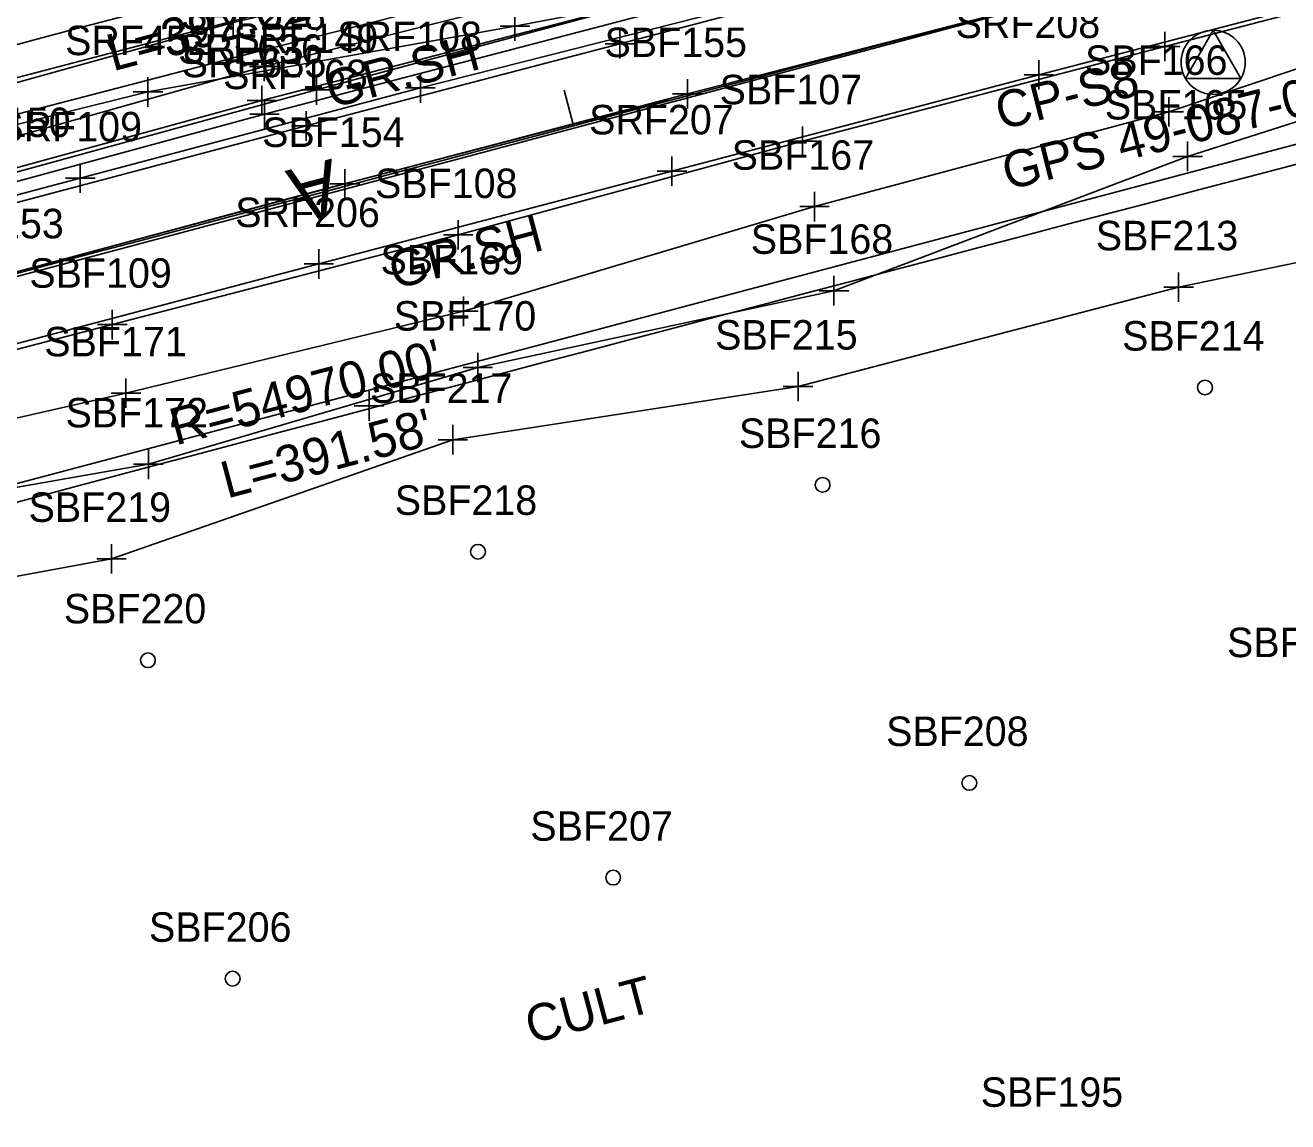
# Model space of a CAD drawing. Extents: x 818717 to 846077, y 440014 to 541392.
# Drawn here: x 831949.3 to 832120.6, y 493055.7 to 493204.5 of the extents above; entities that cross this region are included whole.
import ezdxf

# ---------------------------------------------------------------- set-up
doc = ezdxf.new("R2010")
doc.units = 0
for name, color, linetype in [('SURVEY - CENTERLINE - Preliminary', 7, 'Continuous'), ('SURVEY - CENTERLINE - Preliminary Text', 7, 'Continuous'), ('SURVEY - CONTROL with Text', 7, 'Continuous'), ('SURVEY - DRAINAGE - Area Shapes', 7, 'Continuous'), ('SURVEY - DTM - Breaklines', 7, 'Continuous'), ('SURVEY - DTM - Breaklines - Points - Locators', 7, 'Continuous'), ('SURVEY - DTM - Breaklines - Points - Numbers', 7, 'Continuous'), ('SURVEY - DTM - Spot Points - Locators', 7, 'Continuous'), ('SURVEY - DTM - Spot Points - Point Numbers', 7, 'Continuous'), ('SURVEY - PROPERTY - ROW Lines', 7, 'Continuous'), ('SURVEY - PROPERTY - ROW Lines - Points - Locators', 7, 'Continuous'), ('SURVEY - PROPERTY - ROW Lines Text', 7, 'Continuous'), ('SURVEY - TRAFFIC CONTROL - Pavement Marking - Points - Locators', 7, 'Continuous'), ('SURVEY - TRAFFIC CONTROL - Pavement Marking - Points - Numbers', 7, 'Continuous'), ('SURVEY - TRAFFIC CONTROL - Pavement Marking with Text', 7, 'Continuous'), ('SURVEY - TRANSPORTATION - Features Text', 7, 'Continuous'), ('SURVEY - TRANSPORTATION - Roads', 7, 'Continuous'), ('SURVEY - TRANSPORTATION - Roads - Points - Locators', 7, 'Continuous'), ('SURVEY - TRANSPORTATION - Roads - Points - Numbers', 7, 'Continuous'), ('SURVEY - UTILITIES - Electric (Overhead) with Text', 7, 'Continuous'), ('SURVEY - UTILITIES - Telephone (Underground) - Points - Locators', 7, 'Continuous'), ('SURVEY - UTILITIES - Telephone (Underground) - Points - Numbers', 7, 'Continuous'), ('SURVEY - UTILITIES - Telephone (Underground) with Text', 7, 'Continuous'), ('SURVEY - UTILITIES - Water with Text', 7, 'Continuous'), ('SURVEY - VEGETATION - Features - Points - Locators', 7, 'Continuous'), ('SURVEY - VEGETATION - Features - Points - Numbers', 7, 'Continuous'), ('SURVEY - VEGETATION - Features with Text', 7, 'Continuous')]:
    doc.layers.add(name, color=color, linetype=linetype)

msp = doc.modelspace()

# ---------------------------------------------------------------- linework, layer by layer
at = {"layer": 'SURVEY - CENTERLINE - Preliminary'}
msp.add_arc((846074.62, 440015.93), 55000, 104.635499, 105.043654, dxfattribs=at)
msp.add_arc((846074.62, 440015.93), 55000, 104.635499, 105.043654, dxfattribs=at)
msp.add_arc((846074.62, 440015.93), 55000, 104.635499, 105.043654, dxfattribs=at)
at = {"layer": 'SURVEY - CENTERLINE - Preliminary Text'}
for p, q in [((832023.71, 493190.85), (832022.44, 493195.69)), ((831988.29, 493181.84), (832036.66, 493194.47)), ((831940, 493168.86), (831988.29, 493181.84))]:
    msp.add_line(p, q, dxfattribs=at)
at = {"layer": 'SURVEY - CONTROL with Text'}
for p, q in [((832110.47, 493203.81), (832106.7, 493197.28)), ((832114.24, 493197.28), (832110.47, 493203.81)), ((832110.47, 493199.46), (832110.47, 493199.46)), ((832106.7, 493197.28), (832114.24, 493197.28))]:
    msp.add_line(p, q, dxfattribs=at)
msp.add_circle((832110.47, 493199.46), 4.35, dxfattribs=at)
at = {"layer": 'SURVEY - DRAINAGE - Area Shapes'}
msp.add_lwpolyline([(833331.86, 493535.43), (832825.85, 493400.54), (832121.68, 493216.64), (831495.16, 493049.75), (830960.37, 492909.24), (830124.73, 492686.08), (830069.9, 493396.23), (830870.86, 494031.84), (831248.11, 494413.67), (831536.95, 494545.33), (832050.07, 494534.01), (832097.96, 494614.84), (832139.36, 494784.62), (832167.46, 494840.58), (832274.31, 494844.36), (832647.22, 494804.13), (832934.24, 494910.41), (833081.03, 494456.05), (833331.86, 493535.43)], dxfattribs=at)
at = {"layer": 'SURVEY - DTM - Breaklines'}
for points in [[(831770.96, 493123.4), (831813.86, 493135.07), (831857.39, 493146.73), (831900.86, 493158.47), (831946.48, 493170.59), (831992.71, 493182.98), (832039.15, 493195.18), (832084.76, 493206.97), (832129.99, 493218.78), (832149.29, 493223.98), (832194.39, 493235.62), (832247.61, 493249.75), (832293.49, 493261.68), (832340.52, 493273.78)], [(832142.59, 493248.12), (832139.68, 493247.54), (832108.04, 493238.25), (832059.21, 493226.8), (832016.93, 493214.13), (831977.53, 493204.88), (831934.18, 493192.82), (831885.96, 493181.02), (831841.41, 493171.23), (831796.37, 493166.38), (831801.69, 493181.68), (831795.28, 493183.83), (831789.32, 493168.76), (831775.78, 493173.56), (831765.85, 493166.76)], [(832140.22, 493244.36), (832106.95, 493233.7), (832060.11, 493221.66), (832022.66, 493211.6), (831981.44, 493201.09), (831935.37, 493189.1), (831887.47, 493176.86), (831843.25, 493166.04), (831798.12, 493162.94), (831794.2, 493164.7), (831799.41, 493178.67), (831795.65, 493181.96), (831790.41, 493167.38)], [(832140.95, 493241.96), (832107.3, 493230.3), (832060.96, 493218.28), (832023.31, 493209.39), (831981.76, 493198.9), (831936.65, 493186.2), (831888.63, 493174.71), (831844.24, 493162.67), (831795, 493159.67)], [(832140.88, 493237.3), (832107.45, 493226.49), (832065.3, 493215.2), (832029.04, 493206.5), (831988.85, 493195.72), (831947.28, 493184.33), (831903.99, 493173.8), (831854.37, 493161.21), (831813.24, 493150.7), (831784.54, 493147.95), (831766.05, 493144.17), (831768.61, 493132.98)], [(832195.49, 493218.96), (832149.66, 493208), (832104.44, 493192.76), (832056.4, 493179.89), (832008.79, 493165.69), (831963, 493154.57), (831916.73, 493144.05), (831869.5, 493130.85), (831832.06, 493121.28), (831826.36, 493121.02)], [(832151.95, 493201.02), (832107.01, 493186.71), (832059.04, 493168.48), (832010.73, 493158.07), (831966.04, 493144.93), (831919.68, 493136.81), (831870.53, 493127.95), (831847.89, 493115.55), (831850.33, 493110.02), (831858.04, 493103.05), (831863.88, 493096.65)], [(832157.93, 493179.81), (832105.79, 493168.96), (832054.16, 493155.49), (832007.33, 493148.26), (831961.05, 493132.11), (831918.6, 493124.28), (831870.52, 493116.27), (831853.11, 493112.26), (831850.33, 493110.02)]]:
    msp.add_lwpolyline(points, dxfattribs=at)
at = {"layer": 'SURVEY - DTM - Breaklines - Points - Locators'}
for p, q in [((831977.53, 493206.88), (831977.53, 493202.88)), ((831981.44, 493203.09), (831981.44, 493199.09)), ((831983.44, 493201.09), (831979.44, 493201.09)), ((831981.76, 493200.9), (831981.76, 493196.9)), ((831983.76, 493198.9), (831979.76, 493198.9)), ((831988.85, 493197.72), (831988.85, 493193.72)), ((831990.85, 493195.72), (831986.85, 493195.72)), ((832039.15, 493197.18), (832039.15, 493193.18)), ((832041.15, 493195.18), (832037.15, 493195.18)), ((832104.44, 493194.76), (832104.44, 493190.76)), ((832106.44, 493192.76), (832102.44, 493192.76)), ((832107.01, 493188.71), (832107.01, 493184.71)), ((832109.01, 493186.71), (832105.01, 493186.71)), ((831992.71, 493184.98), (831992.71, 493180.98)), ((831994.71, 493182.98), (831990.71, 493182.98)), ((832056.4, 493181.89), (832056.4, 493177.89)), ((832058.4, 493179.89), (832054.4, 493179.89)), ((832059.04, 493170.48), (832059.04, 493166.48)), ((832105.79, 493170.96), (832105.79, 493166.96)), ((832061.04, 493168.48), (832057.04, 493168.48)), ((832107.79, 493168.96), (832103.79, 493168.96)), ((832008.79, 493167.69), (832008.79, 493163.69)), ((832010.79, 493165.69), (832006.79, 493165.69)), ((832010.73, 493160.07), (832010.73, 493156.07)), ((832012.73, 493158.07), (832008.73, 493158.07)), ((831963, 493156.57), (831963, 493152.57)), ((832054.16, 493157.49), (832054.16, 493153.49)), ((832056.16, 493155.49), (832052.16, 493155.49)), ((831965, 493154.57), (831961, 493154.57)), ((832007.33, 493150.26), (832007.33, 493146.26)), ((832009.33, 493148.26), (832005.33, 493148.26)), ((831966.04, 493146.93), (831966.04, 493142.93)), ((831968.04, 493144.93), (831964.04, 493144.93)), ((831961.05, 493134.11), (831961.05, 493130.11)), ((831963.05, 493132.11), (831959.05, 493132.11))]:
    msp.add_line(p, q, dxfattribs=at)
at = {"layer": 'SURVEY - DTM - Spot Points - Locators'}
for centre in [(832109.36, 493155.35), (832057.49, 493142.14), (832010.75, 493133.06), (831965.98, 493118.34), (832077.4, 493101.7), (832029.09, 493088.85), (831977.47, 493075.14)]:
    msp.add_circle(centre, 1, dxfattribs=at)
at = {"layer": 'SURVEY - PROPERTY - ROW Lines'}
for radius in [55030, 54970]:
    msp.add_arc((846074.62, 440015.93), radius, 104.635499, 105.043649, dxfattribs=at)
at = {"layer": 'SURVEY - PROPERTY - ROW Lines - Points - Locators'}
for p, q in [((831995.97, 493154.84), (831995.97, 493150.84)), ((831997.97, 493152.84), (831993.97, 493152.84))]:
    msp.add_line(p, q, dxfattribs=at)
at = {"layer": 'SURVEY - TRAFFIC CONTROL - Pavement Marking - Points - Locators'}
for p, q in [((832030, 493203.97), (832030, 493199.97)), ((832032, 493201.97), (832028, 493201.97)), ((832086.82, 493199.77), (832086.82, 493195.77)), ((832088.82, 493197.77), (832084.82, 493197.77)), ((831987.46, 493192.83), (831987.46, 493188.83)), ((831989.46, 493190.83), (831985.46, 493190.83)), ((832037.06, 493186.69), (832037.06, 493182.69)), ((832039.06, 493184.69), (832035.06, 493184.69)), ((831989.17, 493174.11), (831989.17, 493170.11)), ((831991.17, 493172.11), (831987.17, 493172.11))]:
    msp.add_line(p, q, dxfattribs=at)
at = {"layer": 'SURVEY - TRAFFIC CONTROL - Pavement Marking with Text'}
for points in [[(832159.39, 493235.77), (832116.7, 493224.52), (832072.63, 493213.17), (832030, 493201.97), (831987.46, 493190.83), (831936.58, 493177.36), (831894.1, 493165.96), (831849.46, 493153.92), (831808.03, 493142.52), (831768.36, 493131.66), (831727.87, 493120.89), (831684.5, 493109.18), (831641.68, 493097.86), (831599.16, 493086.58), (831554.58, 493074.61), (831511.86, 493063.5), (831467.07, 493051.66), (831425.05, 493040.69), (831380.34, 493029.11), (831337.84, 493017.82), (831296.13, 493006.89), (831251.61, 492995.36), (831208.94, 492984.12), (831169.87, 492973.88)], [(831174.64, 492955.97), (831217.88, 492967.4), (831260.2, 492978.43), (831305.6, 492990.16), (831350.87, 493002.2), (831397.34, 493014.25), (831441.59, 493025.83), (831487.77, 493037.91), (831534.41, 493050.33), (831587.19, 493064.38), (831630.52, 493075.92), (831676.82, 493088.3), (831723.86, 493100.96), (831758.43, 493110.25), (831806.28, 493123.18), (831848.98, 493134.67), (831896.65, 493147.52), (831940.52, 493159.26), (831989.17, 493172.11), (832037.06, 493184.69), (832086.82, 493197.77), (832134.83, 493210.3)]]:
    msp.add_lwpolyline(points, dxfattribs=at)
at = {"layer": 'SURVEY - TRANSPORTATION - Roads'}
for points in [[(832337.43, 493283.54), (832290.84, 493271.51), (832245.1, 493259.5), (832196.72, 493246.64), (832147.48, 493233.5), (832099.04, 493220.81), (832050.97, 493208.2), (832002.93, 493195.99), (831956.8, 493183.74), (831911.55, 493171.73), (831864.83, 493159.08), (831817.3, 493145.76), (831768.68, 493132.69)], [(832342.92, 493264.27), (832295.67, 493251.85), (832250.01, 493239.95), (832200.63, 493227.05), (832152.17, 493214.17), (832103.93, 493201.62), (832054.77, 493188.77), (832008.06, 493176.05), (831961.15, 493163.88), (831914.15, 493151.63), (831865.83, 493138.65), (831819.22, 493125.71), (831773.59, 493113.35)]]:
    msp.add_lwpolyline(points, dxfattribs=at)
at = {"layer": 'SURVEY - TRANSPORTATION - Roads - Points - Locators'}
for p, q in [((832103.93, 493203.62), (832103.93, 493199.62)), ((832105.93, 493201.62), (832101.93, 493201.62)), ((832002.93, 493197.99), (832002.93, 493193.99)), ((832004.93, 493195.99), (832000.93, 493195.99)), ((832054.77, 493190.77), (832054.77, 493186.77)), ((832056.77, 493188.77), (832052.77, 493188.77)), ((831956.8, 493185.74), (831956.8, 493181.74)), ((831958.8, 493183.74), (831954.8, 493183.74)), ((832008.06, 493178.05), (832008.06, 493174.05)), ((832010.06, 493176.05), (832006.06, 493176.05)), ((831961.15, 493165.88), (831961.15, 493161.88)), ((831963.15, 493163.88), (831959.15, 493163.88))]:
    msp.add_line(p, q, dxfattribs=at)
at = {"layer": 'SURVEY - UTILITIES - Electric (Overhead) with Text'}
msp.add_lwpolyline([(832667.18, 493331.74), (832415.28, 493266.23), (832147.85, 493195.27), (831907.96, 493131.64), (831666.03, 493064.14), (831375.19, 492986.65), (831101.3, 492913.04)], dxfattribs=at)
at = {"layer": 'SURVEY - UTILITIES - Telephone (Underground) - Points - Locators'}
for p, q in [((831981.43, 493196.27), (831981.43, 493192.27)), ((831983.43, 493194.27), (831979.43, 493194.27)), ((831981.8, 493194.44), (831981.8, 493190.44)), ((831983.8, 493192.44), (831979.8, 493192.44))]:
    msp.add_line(p, q, dxfattribs=at)
at = {"layer": 'SURVEY - UTILITIES - Telephone (Underground) with Text'}
for points in [[(832336.84, 493284.72), (832273.67, 493269.41), (832254.65, 493265.33), (832241.32, 493260.67), (832203.09, 493249.29), (832136.87, 493232.13), (832079.02, 493217.89), (831981.8, 493192.44), (831904.38, 493171.41), (831843.31, 493154.78), (831799.38, 493142.99), (831790.74, 493148.24), (831757.75, 493149.99)], [(832214.24, 493268.88), (832214.09, 493255.37), (832202.72, 493250.84), (832136.43, 493233.69), (832079.13, 493219.64), (831981.43, 493194.27), (831903.88, 493173.04), (831842.73, 493156.61), (831799.25, 493144.57), (831792.09, 493149.13), (831757.2, 493152.41)]]:
    msp.add_lwpolyline(points, dxfattribs=at)
at = {"layer": 'SURVEY - UTILITIES - Water with Text'}
msp.add_lwpolyline([(831168.53, 492982.83), (831221.68, 492997.59), (831271.35, 493010.03), (831320.05, 493023.02), (831382.11, 493039.09), (831464.43, 493059.02), (831521.6, 493075.98), (831637.27, 493105.47), (831699.54, 493130.69), (831734.63, 493142.29), (831763.92, 493149.4), (831800.53, 493157.83), (831844.47, 493169.57), (831878.73, 493177.18), (831933.72, 493193.59), (832000.95, 493211.25), (832058.59, 493225.48), (832113.6, 493238.29), (832172.68, 493261.93), (832217.98, 493273.66), (832269.17, 493287.2), (832330.79, 493299.45)], dxfattribs=at)
at = {"layer": 'SURVEY - VEGETATION - Features - Points - Locators'}
for p, q in [((832015.77, 493206.39), (832015.77, 493202.39)), ((832017.77, 493204.39), (832013.77, 493204.39)), ((831965.98, 493197.44), (831965.98, 493193.44)), ((831967.98, 493195.44), (831963.98, 493195.44))]:
    msp.add_line(p, q, dxfattribs=at)
at = {"layer": 'SURVEY - VEGETATION - Features with Text'}
msp.add_lwpolyline([(831888.55, 493177.45), (831886.32, 493186.52), (831919.88, 493205.25), (831958.38, 493211.98), (831995.55, 493226.97), (832045.5, 493254.8), (832112.46, 493247.88), (832111.49, 493228.36), (832055.54, 493211.96), (832015.77, 493204.39), (831965.98, 493195.44), (831889.31, 493176.37)], dxfattribs=at)

# ---------------------------------------------------------------- texts
at = {"layer": 'SURVEY - CENTERLINE - Preliminary Text'}
msp.add_text('A', height=7.5, rotation=194.8396, dxfattribs=at).set_placement((831990.95, 493186.42))
at = {"layer": 'SURVEY - CONTROL with Text'}
for s, rotation, p in [('CP-S8', 14.2767, (832081.69, 493190.27)), ('GPS 49-087-08', 14.1572, (832082.6, 493182.1))]:
    msp.add_text(s, height=5, rotation=rotation, dxfattribs=at).set_placement(p)
at = {"layer": 'SURVEY - DTM - Breaklines - Points - Numbers'}
for s, p in [('SRF228', (831970.48, 493203.9)), ('SRF149', (831977.6, 493200.72)), ('SBF155', (832027.91, 493200.18)), ('SBF166', (832093.09, 493197.76)), ('SBF165', (832095.77, 493191.71)), ('SRF150', (831935.87, 493189.33)), ('SBF154', (831981.47, 493187.98)), ('SBF167', (832045.16, 493184.89)), ('SBF153', (831935.24, 493175.59)), ('SBF168', (832047.75, 493173.48)), ('SBF213', (832094.55, 493173.96)), ('SBF169', (831997.53, 493170.69)), ('SBF170', (831999.32, 493163.07)), ('SBF171', (831951.92, 493159.57)), ('SBF215', (832042.92, 493160.49)), ('SBF217', (831996.09, 493153.26)), ('SBF172', (831954.8, 493149.93)), ('SBF219', (831949.79, 493137.11))]:
    msp.add_text(s, height=4, dxfattribs=at).set_placement(p)
at = {"layer": 'SURVEY - DTM - Spot Points - Point Numbers'}
for s, p in [('SBF214', (832098.12, 493160.35)), ('SBF216', (832046.14, 493147.14)), ('SBF218', (831999.46, 493138.06)), ('SBF220', (831954.57, 493123.34)), ('SBF209', (832112.35, 493118.76)), ('SBF208', (832066.11, 493106.7)), ('SBF207', (832017.85, 493093.85)), ('SBF206', (831966.12, 493080.14)), ('SBF195', (832078.94, 493057.75))]:
    msp.add_text(s, height=4, dxfattribs=at).set_placement(p)
at = {"layer": 'SURVEY - PROPERTY - ROW Lines Text'}
for s, p in [("L=392.01'", (831961.21, 493198.23)), ("R=54970.00'", (831969.74, 493147.47)), ("L=391.58'", (831976.7, 493140.26))]:
    msp.add_text(s, height=5, rotation=14.8396, dxfattribs=at).set_placement(p)
at = {"layer": 'SURVEY - TRAFFIC CONTROL - Pavement Marking - Points - Numbers'}
for s, p in [('SRF208', (832075.53, 493202.77)), ('SRF168', (831976.18, 493195.83)), ('SRF207', (832025.82, 493189.69)), ('SRF206', (831977.82, 493177.11))]:
    msp.add_text(s, height=4, dxfattribs=at).set_placement(p)
at = {"layer": 'SURVEY - TRANSPORTATION - Features Text'}
for rotation, p in [(14.8338, (831990.87, 493193.21)), (14.8317, (831999.47, 493168.64))]:
    msp.add_text('GR.SH', height=5, rotation=rotation, dxfattribs=at).set_placement(p)
at = {"layer": 'SURVEY - TRANSPORTATION - Roads - Points - Numbers'}
for s, p in [('SRF108', (831991.65, 493200.99)), ('SBF107', (832043.53, 493193.77)), ('SRF109', (831945.55, 493188.74)), ('SBF108', (831996.78, 493181.05)), ('SBF109', (831949.89, 493168.88))]:
    msp.add_text(s, height=4, dxfattribs=at).set_placement(p)
at = {"layer": 'SURVEY - UTILITIES - Telephone (Underground) - Points - Numbers'}
for s, p in [('SRF636', (831970.08, 493199.27)), ('SRF635', (831970.56, 493197.44))]:
    msp.add_text(s, height=4, dxfattribs=at).set_placement(p)
at = {"layer": 'SURVEY - VEGETATION - Features - Points - Numbers'}
msp.add_text('SRF452', height=4, dxfattribs=at).set_placement((831954.74, 493200.44))
at = {"layer": 'SURVEY - VEGETATION - Features with Text'}
msp.add_text('CULT', height=5, rotation=14.9228, dxfattribs=at).set_placement((832017.97, 493066.27))

doc.saveas('drawing.dxf')
